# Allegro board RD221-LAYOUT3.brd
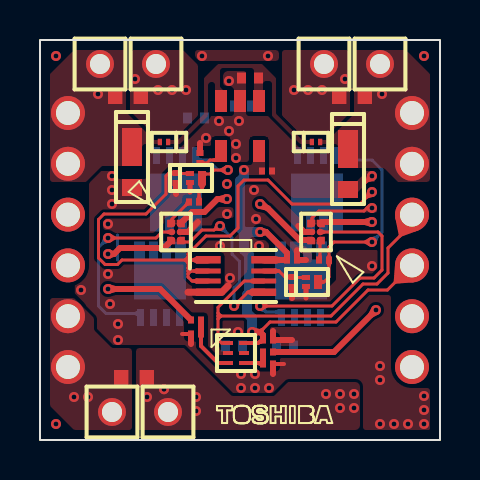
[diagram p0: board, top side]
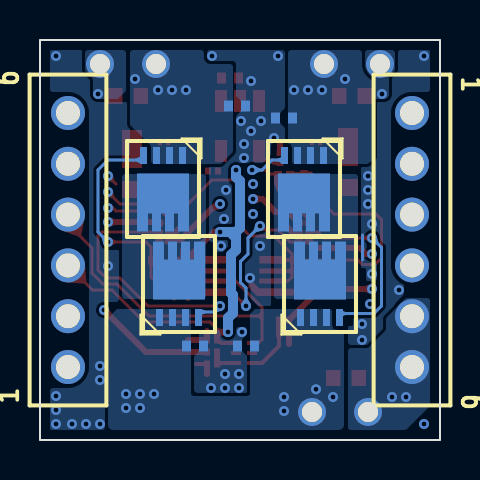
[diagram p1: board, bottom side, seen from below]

Outline 20 x 20 mm; copper layers: TOP, CONDUCTIVE2, CONDUCTIVE3, BOTTOM. Coordinates in mm from the lower left corner of the outline.
Outline path: rectangle 0,0 20,20

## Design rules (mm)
constraint set DEFAULT: 

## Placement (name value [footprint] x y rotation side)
C301  -  [KC00051KD]  10.5 18.1 180 top
C302  -  [KC00540KD]  8 14.1 90 top
C303  -  [KC00540KD]  11.35 13.45 0 top
C304  -  [KC00051KD]  7.8 16.1 0 bottom
C305  -  [KC00051KD]  9.7 4.7 0 bottom
C306  -  [KC00540KD]  11.4 5 0 top
C307  -  [KC00051KD]  10.15 16.7 180 bottom
C308  -  [KC00051KD]  12.25 4.7 180 bottom
C309  -  [KC00540KD]  12.6 9 0 top
CN301  -  [CU12000TD]  1.4 16.35 270 bottom
CN302  -  [CU12000TD]  18.6 3.65 90 bottom
D301  -  [MM02020KD]  4.6 13.9 90 top
D302  -  [MM02020KD]  15.4 13.8 90 top
D303  -  [KC10480CD]  6.2 14.9 0 top
D304  -  [KC10480CD]  13.8 14.9 180 top
DP301  -  [DP002X0KD]  3 18.8 0 top
DP302  -  [DP002X0KD]  5.8 18.8 0 top
DP303  -  [DP002X0KD]  17 18.8 0 top
DP304  -  [DP002X0KD]  14.2 18.8 0 top
DP305  -  [DP002X0KD]  6.4 1.4 0 top
DP306  -  [DP002X0KD]  3.6 1.4 0 top
IC301  -  [MM00631KD]  10 15.7 180 top
IC302  -  [DIC8T60KD]  9.8 8.2 270 top
IC303  -  [LA10251KD]  9.8 4.35 270 top
IC304  -  [BA10620KD]  6.8 10.4 270 top
IC305  -  [BA10620KD]  13.8 10.4 90 top
JP301  -  [KC00081KD]  4.4 17.2 0 top
JP302  -  [KC00081KD]  15.6 17.2 180 top
JP303  -  [KC00081KD]  4.7 3.1 180 top
NOREF  -  []  8 0 0 top
Q301  -  [LA10710KD]  7.8 13.1 0 top
Q302  -  [LA10710KD]  13.6 7.9 0 top
Q303  -  [SN00611KD]  6.8 12.55 0 bottom
Q304  -  [SN00611KD]  6 7.8 180 bottom
Q305  -  [SN00611KD]  13.85 12.55 0 bottom
Q306  -  [SN00611KD]  13.05 7.8 180 bottom
R301  -  [KC00540KD]  7.8 6 0 top
R302  -  [KC00540KD]  7.8 5.3 180 top
R303  -  [KC00540KD]  11.4 4.4 180 top
R304  -  [KC00540KD]  11.4 3.8 0 top
R305  -  [KC00540KD]  7.7 11.9 180 top
R306  -  [KC00540KD]  14.2 9 180 top
R307  -  [KC00540KD]  6.8 13.1 270 top
R308  -  [KC00540KD]  12.6 7.9 270 top

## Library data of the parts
C301 C304 C305 C307 C308 = DP0000016125
C302 = DP0010383000
C303 = DP0007093000
C306 C309 = DP0000015403
CN301 CN302 = DP0010563000
D301 = DP0010580000
D302 = DP0010558000
D303 D304 = DP0010560000
DP301-DP306 = DP9000817000
IC301 = DP0008120000
IC302 = DP0001429000
IC303 = DP0010561000
IC304 = DP0010579000
IC305 = DP0010556000
JP301-JP303 = DP0001376000
Q301 Q302 = DP0010513000
Q303-Q306 = DP0010582000
R301 = DP0000151160
R302 = DP0000151148
R303 R304 = DP0000152120
R305 R306 = DP0000155124
R307 R308 = DP0002867000

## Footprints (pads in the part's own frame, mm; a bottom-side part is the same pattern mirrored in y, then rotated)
BA10620KD
  round 0.325 smd: A1(-0.4,-0.2) A2(-0.4,0.2) B1(0,-0.2) B2(0,0.2) C1(0.4,-0.2) C2(0.4,0.2)
CU12000TD
  round 1.7 hole 1.2: 1(0,0) 2(2.54,0) 3(5.08,0) 4(7.62,0) 5(10.16,0) 6(12.7,0)
DIC8T60KD
  rect 0.375x1.24 smd: 1(-0.812,-1.385) 4(0.812,-1.385) 5(0.812,1.385) 8(-0.812,1.385)
  rect 0.25x1.24 smd: 2(-0.25,-1.385) 3(0.25,-1.385) 6(0.25,1.385) 7(-0.25,1.385)
DP002X0KD
  round 1.397 hole 1: 1(0,0)
KC00051KD
  rect 0.45x0.55 smd: 1(-0.425,0) 2(0.425,0)
KC00081KD
  rect 0.72x0.8 smd: 1(-0.64,0) 2(0.64,0)
KC00540KD
  rect 0.3x0.35 smd: 1(-0.25,0) 2(0.25,0)
KC10480CD
  rect 0.21x0.32 smd: A(-0.205,0) C(0.205,0)
LA10251KD
  rect 0.2x0.5 smd: 1(-0.5,-0.4) 2(0,-0.4) 3(0.5,-0.4) 4(0.5,0.4) 5(0,0.4) 6(-0.5,0.4)
LA10710KD
  rect 0.4x0.7 smd: D(0.3,0)
  rect 0.4x0.25 smd: G(-0.3,0.225) S(-0.3,-0.225)
MM00631KD
  rect 0.6x1.1 smd: 1(-0.95,-1.25) 2(0,-1.25) 3(0.95,-1.25) 4(0.95,1.25) 5(-0.95,1.25)
MM02020KD
  rect 0.85x1 smd: A(-1.275,0)
  rect 1.9x1 smd: C(0.75,0)
SN00611KD
  rect 0.35x0.85 smd: 1(-0.975,-1.675) 2(-0.325,-1.675) 3(0.325,-1.675) 4(0.975,-1.675)
  custom 0.65x0.65 smd: 5(0,0.675)

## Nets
GND: C301.2 C302.2 C303.2 C304.2 C305.2 C306.2 C307.2 C308.2 C309.2 CN301.3 CN301.4 D301.A D302.A IC301.2 IC302.4 IC303.2 IC304.B2 IC305.B2 Q301.S Q302.S R302.2 R304.2 R307.2 R308.2
VINA: CN301.1 CN301.2 D301.C D303.A DP301.1 JP301.1 R301.1
VINB: CN302.5 CN302.6 D302.C D304.A DP303.1 JP302.1 R303.1
EN20V: CN302.1 IC302.1 IC302.2 IC302.3 Q301.G R307.1
FLAG: CN302.4 IC302.6 IC303.1
LDO-VOUT: C303.1 C306.1 C309.1 CN302.3 IC301.5 IC302.8 IC303.6
SIG190: IC304.A1 R305.2
SIG191: IC305.B1 Q306.4
SIG192: IC305.A1 R306.2
SIG193: C307.1 DP304.1 IC305.A2 JP302.2 Q305.1 Q305.2 Q305.3
SIG195: C301.1 D303.C D304.C IC301.1 IC301.3
SIG196: IC303.4 R303.2 R304.1
SIG203: C305.1 C308.1 DP305.1 IC304.C1 IC305.C1 JP303.1 Q304.1 Q304.2 Q304.3 Q306.1 Q306.2 Q306.3
SIG204: IC302.7 Q302.G R308.1
SIG205: C304.1 DP302.1 IC304.A2 JP301.2 Q303.1 Q303.2 Q303.3
SIG206: Q301.D Q303.4 R305.1
SIG207: Q303.5 Q304.5
SIG208: IC304.B1 Q304.4
SIG209: IC302.5 IC304.C2
SIG210: Q305.5 Q306.5
SIG211: Q302.D Q305.4 R306.1
SIG213: IC303.3 R301.2 R302.1
SIG214: C302.1 IC301.4
VCT5V: CN302.2 IC305.C2
VOUT: CN301.5 CN301.6 DP306.1 JP303.2

Pads without a net: IC303 5

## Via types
v1: diameter 0.5, hole 0.25, TOP to BOTTOM, 82 vias

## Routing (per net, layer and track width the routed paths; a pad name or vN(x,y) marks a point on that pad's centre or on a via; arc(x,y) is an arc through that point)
GND: length 21.4
  TOP w0.15: v1(16.6,13.2) 16.2,12.8
  TOP w0.2: R302.2 7.1,5.3 ; 12.2,3.8 R304.2
  TOP w0.25: Q301.S 7.5,12.4 ; Q302.S 13.3,7.1
  TOP w0.3: R308.2 12.6,7.1 ; 12.92,10.7 13.22,10.4 IC305.B2 ; IC304.B2 7.4,10.4 7.9,10.9 ; C302.2 8,14.85 ; R304.2 11.65,3.3 ; 12.6,5 C306.2 11.65,5.45 ; 13.3,9 C309.2 12.85,9.49 ; R302.2 7.55,4.8 ; R307.2 6.8,12.3
  TOP w0.35: 9.41,7.71 9.09,7.39 IC302.4 7.4,7.39
  CONDUCTIVE2 w0.15: 3.35,0.57 3.9,0.57 ; 6.15,0.57 6.67,0.57
  CONDUCTIVE2 w1: CN301.3 2.5,11.27 ; CN301.3 CN301.4 ; CN301.3 1.4,12.45 ; CN301.4 2.4,8.73 ; CN301.4 1.4,7.55
  CONDUCTIVE3 w0.15: 6.17,0.57 6.62,0.57
  BOTTOM w0.15: 3.88,10.25 3.88,9
  vias: v1(0.8,19.2) v1(0.8,0.8) v1(2.05,7.5) v1(3.4,10.8) v1(3.4,8.3) v1(3.5,6.8) v1(3.6,13.2) v1(3.6,12.5) v1(3.6,11.8) v1(3.9,5.8) v1(3.9,5) v1(8.1,19.2) v1(8.3,15.1) v1(8.95,15.95) v1(9,9.7) v1(9.35,12.8) v1(9.35,11.3) v1(9.45,17.95) v1(9.45,15.45) v1(9.5,8.1) v1(9.8,14.8) v1(9.8,14.1) v1(9.95,15.95) v1(9.9,5.4) v1(10.05,3.3) v1(10.05,2.6) v1(10.7,12.5) v1(10.8,11.05) v1(10.75,3.3) v1(10.75,2.6) v1(10.95,9.7) v1(11.4,19.2) v1(11.45,2.6) v1(16.6,8.7) v1(17,3.7) v1(17,3) v1(17,0.8) v1(17.7,0.8) v1(18.4,0.8) v1(19.2,19.2) v1(19.2,2.2) v1(19.2,1.5) v1(19.2,0.8)
VINA: length 15.2
  TOP w0.3: R301.1 6,7.55 v1(3.4,7.55)
  CONDUCTIVE3 w0.6: v1(2.9,17.3) 2.65,17.05 2.65,7.95 3.05,7.55 v1(3.4,7.55)
VINB: length 17.2
  TOP w0.3: R303.1 14.7,4.4 v1(16.8,6.5)
  CONDUCTIVE3 w0.6: v1(17.1,17.3) 17.35,16.79 17.35,6.85 17,6.5 v1(16.8,6.5)
EN20V: length 41.1
  TOP w0.15: 7.55,8.45 7.83,8.45 ; 7.55,8.45 7.4,8.3 ; 7.55,8.45 7.4,8.6 ; 7.55,8.45 7.4,8.45 ; 7.55,9 7.4,9.15 ; 7.55,9 7.4,8.85 ; 7.55,9 7.4,9 ; 7.55,9 7.87,9 ; 7.4,9.15 7.25,9 ; 7.4,9.15 7.4,9.3 8.3,10.2 9.5,10.2 9.9,10.6 9.9,12.7 10.2,13 11.4,13 12.6,11.8 16,11.8 v1(16.6,12.4) ; 7.4,9.15 7.4,9 ; 7.4,8.3 7.4,8.15 7.6,7.95 7.83,7.95 ; 7.4,8.3 7.4,8.45 ; 7.4,8.45 7.4,8.6 ; 7.25,9 4.1,9 3.88,8.78 3.25,8.78 2.92,9.1 2.92,11.03 3.2,11.3 5.3,11.3 6.3,12.3 6.3,13.2 6.45,13.35 R307.1 7.1,13.32 7.42,13.32 ; 7.25,9 7.4,8.85 ; 7.25,9 7.4,9 ; 7.4,8.85 7.4,8.6 ; 7.4,8.85 7.4,9
  TOP w0.25: IC302.3 7.83,7.95 ; 7.83,8.45 IC302.2 ; Q301.G 7.42,13.32
  TOP w0.35: 7.87,9 8.4,9
  CONDUCTIVE2 w0.15: v1(16.6,12.4) 16.05,11.85 16.05,10.8 16.5,10.35 16.8,10.35 17.25,9.9 17.25,5 CN302.1
FLAG: length 18.2
  TOP w0.15: 9.05,6.2 14.55,6.2 16.15,7.8 16.85,7.8 17.4,8.35 17.4,9.6 18,10.2 CN302.4 ; 9.05,6.2 8.9,6.05 ; 9.05,6.2 8.9,6.2 ; 9.05,6.2 8.9,6.35 ; 8.9,6.2 8.9,6.35 ; 8.9,6.2 8.9,6.05 ; 8.9,6.35 8.9,6.63 10.22,7.95 10.69,7.95 ; 8.9,6.05 8.9,5.03 9.07,4.85 9.25,4.85
  TOP w0.2: 9.25,4.85 IC303.1
  TOP w0.25: IC302.6 10.69,7.95
LDO-VOUT: length 23.9
  TOP w0.15: CN302.3 17.37,7.5 16.4,7.5 14.8,5.9 11.5,5.9 11,5.4
  TOP w0.2: C306.1 10.9,4.85 IC303.6
  TOP w0.3: v1(11,10.4) 11.31,10.4 12.35,9.36 C309.1 11.79,9 ; C306.1 11.15,5.25 11,5.4 v1(10.6,5.4)
  TOP w0.35: 11.79,9 11.19,9
  BOTTOM w0.5: 10.2,10.1 10.2,10.4 ; 10.2,10.1 10.5,10.4 ; 10.2,10.1 10.2,9.5 10.45,9.25 10.45,7.35 10.35,7.25 10.35,6.35 10.6,6.1 v1(10.6,5.4) ; 10.2,10.4 10,10.6 10,12.95 10.2,13.15 v1(10.2,13.5) ; 10.2,10.4 10.5,10.4 ; 10.5,10.4 v1(11,10.4)
SIG190: length 1.5
  TOP w0.15: IC304.A1 6.6,11.05 R305.2
SIG191: length 12.9
  TOP w0.15: IC305.B1 16.9,10.4 17.1,10.2 17.1,8.5 16.7,8.1 16,8.1 14.6,6.7 v1(11,6.7)
  BOTTOM w0.15: v1(11,6.7) 11.3,6.4 11.98,6.4
  BOTTOM w0.3: 11.98,6.4 12.07,6.4
SIG192: length 1
  TOP w0.15: IC305.A1 14,9.2 R306.2
SIG193: length 9.9
  TOP w0.3: IC305.A2 12.98,10 11.4,11.58 v1(11,11.8)
  CONDUCTIVE3 w0.6: v1(11,11.8) 11.3,11.8 11.9,12.4 11.9,16.7 v1(12.7,17.5)
  vias: v1(13.4,17.5) v1(14.1,17.5) v1(15.25,18.05)
SIG196: length 1.6
  TOP w0.2: R304.1 10.9,3.85 IC303.4
  TOP w0.3: R303.2 R304.1
SIG203: length 28.1
  TOP w0.3: IC304.C1 6.2,9.6 4,9.6 3.7,9.3 v1(3.4,9.3) ; IC305.C1 14.1,10.9 v1(16.6,10.9)
  CONDUCTIVE3 w0.5: 5.35,8.35 5.9,8.9 ; 5.35,8.35 v1(5.35,2.15) ; 5.35,8.35 5.35,9.1 ; 5.9,8.9 5.55,8.9 5.35,9.1 ; 5.9,8.9 11.3,8.9 13.3,10.9 v1(16.6,10.9) ; 5.35,9.1 5.15,9.3 v1(3.4,9.3)
  vias: v1(6.2,2.54) v1(7.8,2.15) v1(7.8,1.45) v1(14.3,2.3) v1(15,2.3) v1(15,1.6) v1(15.7,2.3) v1(15.7,1.6)
SIG204: length 2.2
  TOP w0.15: 11.77,8.45 11.95,8.45 12.25,8.15 R308.1 12.9,8.12 13.22,8.12
  TOP w0.25: 11.77,8.45 IC302.7 ; Q302.G 13.22,8.12
SIG205: length 9.6
  TOP w0.3: IC304.A2 7.6,11.4 8.22,11.4 8.87,12.05 v1(9.35,12.05)
  CONDUCTIVE3 w0.6: v1(9.35,12.05) 8.65,12.05 7.3,13.4 v1(7.3,17.5)
  vias: v1(4.75,18.05) v1(5.9,17.5) v1(6.6,17.5)
SIG206: length 4.5
  TOP w0.15: v1(9.4,13.5) 8.7,13.5 8.5,13.3 8.1,13.3 ; 7.95,11.99 7.95,12.35 8.1,12.5 8.1,12.84
  TOP w0.3: R305.1 7.95,11.99
  TOP w0.4: 8.1,12.84 Q301.D
  BOTTOM w0.15: 7.87,14 8.4,14 8.9,13.5 v1(9.4,13.5)
  BOTTOM w0.3: 7.87,14 7.78,14
SIG208: length 9.2
  TOP w0.15: IC304.B1 6.1,10.4 5.8,10.1 v1(3.4,10.1)
  BOTTOM w0.15: v1(3.4,10.1) 2.92,9.62 2.92,6.7 3.3,6.33 4.95,6.33
  BOTTOM w0.3: 5.05,6.33 4.95,6.33
SIG209: length 8.6
  TOP w0.15: v1(9.7,6.7) 10.39,7.39 10.65,7.39 ; IC304.C2 7.25,9.9 7.5,9.9 8.1,10.5 8.7,10.5 v1(9,10.7)
  TOP w0.37: 10.65,7.39 IC302.5
  BOTTOM w0.15: v1(9.7,6.7) 9.7,7.6 9.97,7.88 9.97,8.93 9.6,9.3 9.6,10.1 v1(9,10.7)
SIG211: length 10.7
  TOP w0.15: 14.45,8.9 14.45,8.15 14.2,7.9 Q302.D ; 14.45,9.02 14.45,9.65 14.7,9.9 v1(16.6,9.9)
  TOP w0.3: 14.45,9.02 R306.1 14.45,8.9
  BOTTOM w0.15: 14.93,14 16.6,14 17.1,13.5 17.1,10.4 v1(16.6,9.9)
  BOTTOM w0.35: 14.82,14 14.93,14
SIG213: length 3
  TOP w0.2: R302.1 8.05,4.7 8.9,3.85 IC303.3
  TOP w0.3: R302.1 R301.2
SIG214: length 1.1
  TOP w0.15: 8.02,13.85 8.35,13.85 8.5,14 8.77,14
  TOP w0.2: 8.77,14 9,14
  TOP w0.3: C302.1 8.02,13.85
VCT5V: length 9.7
  TOP w0.15: v1(16.6,11.6) 16.35,11.6 16.2,11.45 13.95,11.45 13.6,11.1 IC305.C2
  CONDUCTIVE2 w0.15: CN302.2 17.65,7.14 17.65,10.55 v1(16.6,11.6)
VOUT:
  vias: v1(1.7,2.15) v1(2.4,2.15)

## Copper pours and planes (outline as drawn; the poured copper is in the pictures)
GND on TOP: 8.02,18.95 7.92,18.99 7.79,19.12 7.75,19.22 7.75,19.35 7.79,19.46 7.9,19.5 11.8,19.5 11.91,19.46 11.95,19.35 11.95,19.1 11.91,18.99 11.8,18.95
GND on TOP: 3.79,10.35 3.77,10.35 3.75,10.36 3.5,10.49 3.4,10.5 3.3,10.5 3.19,10.54 3.15,10.65 3.15,10.9 3.16,10.93 3.17,10.95 3.27,11.05 3.3,11.07 3.32,11.07 5.3,11.07 5.39,11.09 5.46,11.14 6.46,12.14 6.52,12.24 6.53,12.3 6.53,12.35 6.57,12.46 6.67,12.5 7.55,12.5 7.6,12.48 7.62,12.43 7.62,12.35 7.6,12.3 7.55,12.28 7.33,12.28 7.17,12.21 7.1,12.05 7.1,11.9 7.09,11.87 7.08,11.85 6.44,11.21 6.4,11.17 6.38,11.16 6.26,11.08 6.21,10.94 6.21,10.91 6.2,10.89 6.19,10.86 5.7,10.37 5.67,10.36 5.64,10.35
GND on TOP: 12.53,6.92 12.47,6.95 12.45,7 12.45,7.22 12.47,7.28 12.53,7.3 14.04,7.3 14.1,7.31 14.14,7.34 14.76,7.96 14.79,8 14.8,8.06 14.8,9.27 14.81,9.3 14.82,9.32 14.98,9.48 15,9.49 15.03,9.5 16.8,9.5 16.85,9.48 16.88,9.43 16.88,8.62 16.87,8.6 16.85,8.57 16.63,8.35 16.6,8.33 16.58,8.32 16,8.32 15.91,8.31 15.84,8.26 14.53,6.95 14.5,6.93 14.48,6.92
GND on TOP: outline of 298 points within 1.74,0.5 19.5,18.45
GND on TOP: outline of 88 points within 7.93,7.4 13.6,12.78
GND on TOP: 9.28,5.15 9.17,5.19 9.12,5.3 9.12,5.9 9.15,5.95 9.2,5.97 10.12,5.97 10.18,5.95 10.2,5.9 10.2,5.3 10.16,5.19 10.05,5.15
GND on BOTTOM: outline of 95 points within 7.75,9.4 11.65,19.5 ; 1 cut-out
GND on BOTTOM: 16.9,0.5 16.79,0.54 16.75,0.65 16.75,6.03 16.77,6.08 16.82,6.1 17.2,6.51 16.8,6.9 16.2,6.9 16.09,6.94 16.05,7.05 16.05,9.43 16.07,9.48 16.12,9.5 16.6,9.5 16.84,9.58 16.99,9.79 17.04,10.01 17.06,10.05 17.26,10.24 17.31,10.31 17.32,10.4 17.32,13.5 17.31,13.59 17.26,13.66 16.76,14.16 16.69,14.21 16.6,14.22 15.57,14.22 15.52,14.25 15.5,14.3 15.5,15.51 15.51,15.54 15.52,15.56 15.56,15.6 15.63,15.7 15.65,15.81 15.65,16.82 15.67,16.88 15.72,16.9 17.1,16.9 17.38,17.02 17.5,17.3 17.5,17.96 17.51,17.99 17.52,18.01 17.81,18.3 17.86,18.35 17.88,18.42 17.9,18.46 17.9,18.51 17.9,19.35 17.89,19.41 17.91,19.47 17.97,19.5 19.43,19.5 19.48,19.48 19.5,19.43 19.5,17.55 19.46,17.44 19.35,17.4 18.6,17.4 17.86,17.09 17.55,16.35 17.55,3.65 17.86,2.91 18.6,2.6 19.35,2.6 19.46,2.56 19.5,2.45 19.5,0.57 19.48,0.52 19.43,0.5
GND on BOTTOM: outline of 105 points within 0.5,4.75 4.6,19.5
GND on CONDUCTIVE2: outline of 155 points within 0.5,0.5 19.5,19.5 ; 22 cut-outs
GND on CONDUCTIVE3: outline of 115 points within 0.5,0.5 19.5,10.5 ; 6 cut-outs
GND on CONDUCTIVE3: outline of 101 points within 0.5,9.3 19.5,19.5 ; 7 cut-outs
VINA on BOTTOM: 2.8,17.05 2.62,17.12 2.55,17.3 2.55,18.09 2.51,18.19 2.29,18.41 2.25,18.51 2.25,19.35 2.29,19.46 2.4,19.5 3.6,19.5 3.7,19.47 3.75,19.38 3.75,19.35 3.75,18.8 3.67,18.46 3.44,18.2 3.34,18.12 3.27,18.04 3.25,17.94 3.25,17.12 3.23,17.07 3.17,17.05
VINB on TOP: 17.92,12.9 17.88,12.91 17.86,12.94 17.24,13.56 17.14,13.6 15.05,13.6 14.94,13.64 14.9,13.75 14.9,14.65 14.86,14.76 14.75,14.8 13.97,14.8 13.92,14.82 13.9,14.88 13.9,14.93 13.92,14.98 13.97,15 14.28,15 14.39,15.02 14.49,15.09 15.66,16.26 15.69,16.3 15.7,16.36 15.7,19.35 15.74,19.46 15.85,19.5 18.24,19.5 18.3,19.49 18.34,19.46 19.46,18.34 19.49,18.3 19.5,18.24 19.5,13.05 19.46,12.94 19.35,12.9
VINB on BOTTOM: 16.16,17.05 16.06,17.09 15.74,17.41 15.7,17.51 15.7,19.35 15.74,19.46 15.85,19.5 17.6,19.5 17.71,19.46 17.75,19.35 17.75,18.51 17.71,18.41 17.39,18.09 17.35,17.99 17.35,17.3 17.32,17.18 17.23,17.08 17.1,17.05
LDO-VOUT on TOP: 10.1,13.25 9.99,13.29 9.95,13.4 9.95,13.6 9.99,13.71 10.1,13.75 10.49,13.75 10.55,13.76 10.59,13.79 10.61,13.81 10.65,13.91 10.65,14.75 10.69,14.86 10.8,14.9 11.1,14.9 11.21,14.86 11.25,14.75 11.25,13.4 11.21,13.29 11.1,13.25
SIG193 on TOP: 13.01,15.35 12.98,15.36 12.95,15.37 12.12,16.2 12.11,16.23 12.1,16.26 12.1,19.35 12.14,19.46 12.25,19.5 15.35,19.5 15.46,19.46 15.5,19.35 15.5,16.41 15.46,16.31 14.54,15.39 14.44,15.35
SIG193 on BOTTOM: 11.01,13.8 10.95,13.81 10.91,13.84 10.39,14.36 10.35,14.46 10.35,18.65 10.39,18.76 10.5,18.8 11.54,18.8 11.64,18.84 11.76,18.96 11.8,19.06 11.8,19.35 11.84,19.46 11.95,19.5 15.35,19.5 15.46,19.46 15.5,19.35 15.5,15.81 15.49,15.75 15.46,15.71 14.49,14.74 14.46,14.7 14.45,14.64 14.45,13.93 14.43,13.87 14.38,13.85 14.35,13.81 14.3,13.8
SIG195 on TOP: outline of 82 points within 6.3,14.8 13.7,18.8
SIG203 on TOP: 5.05,0.5 4.92,0.53 4.83,0.62 4.8,0.75 4.8,4.45 4.84,4.56 4.95,4.6 7.16,4.6 7.19,4.59 7.21,4.58 9.54,2.24 9.65,2.2 11.64,2.2 11.7,2.21 11.74,2.24 12.36,2.86 12.4,2.89 12.46,2.9 15.75,2.9 15.93,2.83 16,2.65 16,0.75 15.93,0.57 15.75,0.5
SIG203 on BOTTOM: 5.05,0.5 4.92,0.53 4.83,0.62 4.8,0.75 4.8,5.35 4.84,5.46 4.95,5.5 5.12,5.5 5.26,5.54 5.36,5.64 5.4,5.78 5.4,6.4 5.44,6.51 5.55,6.55 9.19,6.55 9.25,6.54 9.29,6.51 9.46,6.34 9.49,6.3 9.5,6.24 9.5,2.35 9.54,2.24 9.65,2.2 12.3,2.2 12.41,2.24 12.45,2.35 12.45,6.47 12.47,6.53 12.53,6.55 16.09,6.55 16.15,6.54 16.19,6.51 16.56,6.14 16.59,6.1 16.6,6.04 16.6,0.75 16.57,0.62 16.48,0.53 16.35,0.5
SIG203 on CONDUCTIVE3: 7.65,1 7.54,1.04 7.5,1.15 7.5,2.3 7.54,2.41 7.65,2.45 9.39,2.45 9.45,2.44 9.49,2.41 9.76,2.14 9.86,2.1 11.74,2.1 11.84,2.14 12.26,2.56 12.36,2.6 15.85,2.6 15.96,2.56 16,2.45 16,1.15 15.96,1.04 15.85,1
SIG205 on TOP: 4.54,16.41 4.51,16.45 4.5,16.51 4.5,19.35 4.54,19.46 4.65,19.5 7.09,19.5 7.19,19.46 7.86,18.79 7.9,18.69 7.9,16.26 7.89,16.23 7.88,16.2 7.05,15.37 7.02,15.36 6.99,15.35 5.66,15.35 5.6,15.36 5.56,15.39
SIG205 on BOTTOM: 3.66,13.8 3.6,13.81 3.56,13.84 3.34,14.06 3.31,14.1 3.3,14.16 3.3,16.84 3.31,16.9 3.34,16.94 3.36,16.96 3.39,17 3.4,17.06 3.4,17.94 3.41,17.98 3.43,18 3.8,18.39 3.9,18.8 3.9,19.35 3.94,19.46 4.05,19.5 7.45,19.5 7.56,19.46 7.6,19.35 7.6,14.89 7.59,14.85 7.44,14.72 7.4,14.57 7.4,13.95 7.36,13.84 7.25,13.8
SIG207 on BOTTOM: 4.25,7.05 4.14,7.09 4.1,7.2 4.1,13.15 4.14,13.26 4.25,13.3 8.15,13.3 8.26,13.26 8.3,13.15 8.3,7.2 8.26,7.09 8.15,7.05
SIG210 on BOTTOM: 11.85,7.05 11.74,7.09 11.7,7.2 11.7,13.15 11.74,13.26 11.85,13.3 15.75,13.3 15.86,13.26 15.9,13.15 15.9,7.2 15.86,7.09 15.75,7.05
VOUT on TOP: 1.8,0.5 1.71,0.52 1.63,0.57 0.57,1.63 0.52,1.71 0.5,1.8 0.5,6.95 0.54,7.06 0.65,7.1 1.6,7.1 1.69,7.08 1.77,7.03 2.66,6.14 2.7,6.04 2.7,5.56 2.74,5.46 3.56,4.64 3.66,4.6 4.45,4.6 4.56,4.56 4.6,4.45 4.6,0.65 4.56,0.54 4.45,0.5
VOUT on BOTTOM: 1.8,0.5 1.71,0.52 1.63,0.57 0.57,1.63 0.52,1.71 0.5,1.8 0.5,6.95 0.54,7.06 0.65,7.1 1.64,7.1 1.7,7.09 1.74,7.06 2.66,6.14 2.7,6.04 2.7,5.56 2.74,5.46 3.56,4.64 3.66,4.6 4.45,4.6 4.56,4.56 4.6,4.45 4.6,0.65 4.56,0.54 4.45,0.5

Small or netless copper shapes (teardrops, artwork), in the pictures only: 64 on TOP, 12 on BOTTOM, 4 on CONDUCTIVE2, 3 on CONDUCTIVE3

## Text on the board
Ref Des/Silkscreen Bottom: 1 | 6
SYMBOL-2-TOP: IC301 | IC302 | IC303 | MUX3 | D301 | IC304 | D302 | IC305 | VINA | VOUT | GND | FLAG | VINB
SYMBOL-2-BOTTOM: 1 | Q303 | Q304 | Q306 | Q305
User.5: 1 | 6
